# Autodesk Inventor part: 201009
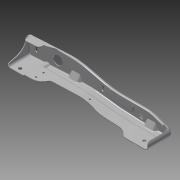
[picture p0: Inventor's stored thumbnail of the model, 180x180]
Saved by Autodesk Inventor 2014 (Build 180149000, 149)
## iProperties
Created: 2007-10
Part Number: 201009
Document SubType Name: Modeling
Designer: MM
Density: 7.85 g/cm^3
Mass: 1039.33 g
Surface Area: 1235.3 cm^2
Volume: 132.398 cm^3
Material: Steel
Description: TOP FRAME RIGHT SIDE PLATE
Appearance: Steel
Component Category: Lower Component
Author: MM
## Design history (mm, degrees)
sketch "Sketch2"
  geometry: L1 (-10, 0)-(-202.66, 0); L2 (-453.629, -13.843)-(-362.619, -13.843); L3 (-357.385, -13.706)-(-296.395, -10.51); L4 (-293.614, -10.266)-(-217.285, -0.894); L5 (-462.692, -8.069)-(-464.267, -4.692); L6 (-462.96, 10.251)-(-460.669, 13.523); L7 (-455.791, 17.222)-(-418.085, 30.463); L8 (-384.952, 36.111)-(-306.589, 36.111); L9 (-248.228, 43.019)-(-193.772, 56.092); L10 (-135.411, 63)-(-10, 63); L11 (0, 10)-(0, 53); A1 r 10 centre (-452.477, 7.787) between (-455.791, 17.222) and (-460.669, 13.523); A2 r 15 centre (-450.673, 1.647) between (-462.96, 10.251) and (-464.267, -4.692); A3 r 10 centre (-453.629, -3.843) between (-462.692, -8.069) and (-453.629, -13.843); A4 r 40 centre (-298.488, 29.435) between (-296.395, -10.51) and (-293.614, -10.266); A5 r 120 centre (-202.66, -120) between (-202.66, 0) and (-217.285, -0.894); A6 r 250 centre (-306.589, 286.111) between (-306.589, 36.111) and (-248.228, 43.019); A7 r 250 centre (-135.411, -187) between (-135.411, 63) and (-193.772, 56.092); A8 r 10 centre (-10, 53) between (0, 53) and (-10, 63); A9 r 10 centre (-10, 10) between (-10, 0) and (0, 10); A10 r 100 centre (-384.952, -63.889) between (-384.952, 36.111) and (-418.085, 30.463); A11 r 100 centre (-362.619, 86.157) between (-362.619, -13.843) and (-357.385, -13.706); 11 further points
  constraints: 22 end point, 22 point on circle, 22 point on line, 22 tangent, 11 centre point, 5 equal radius, 3 parallel, 1 horizontal, 1 perpendicular
  dimensions: "d0" = 210 distance of point (0, 0) point (-210, 0); "d1" = 85 horizontal distance of point (-210, 0) point (-295, -10.437); "d2" = 7 deg angle of L4 L1; "d3" = 65 horizontal distance of point (-360, -13.843) point (-295, -10.437); "d4" = 4 deg angle of L4 L3; "d5" = 460 horizontal distance of point (0, 0) point (-460, -13.843); "d6" = 65 deg angle of L5 L2; "d7" = 120 deg angle of L5 L6; "d8" = 17 vertical distance of point (-460, -13.843) point (-467.927, 3.157); "d9" = 30 vertical distance of point (-460, -13.843) point (-458.825, 16.157); "d10" = 63 distance of point (0, 0) point (0, 63); "d11" = 165 distance of point (-165, 63) point (0, 63); "d12" = 112 horizontal distance of point (-165, 63) point (-277, 36.111); "d13" = 13.5 deg angle of L10 L9; "d14" = 125 distance of point (-402, 36.111) point (-277, 36.111); "d15" = 10 radius of A1; "d16" = 15 radius of A2; "d17" = 40 radius of A4; "d18" = 120 radius of A5; "d19" = 250 radius of A6; "d26" = 100 radius of A10
extrude "Extrusion1" new body sketch "Sketch2" distance "d20" = 80; taper "d21" = 0 deg
sketch "Sketch3"
  geometry: L1 (0, 0)-(125.411, 0) reference; L2 (-10, 0)-(-10, -80) reference; L3 (125.411, 0)-(-10, -8.282); L4 (125.411, 0)-(-10, 0); L5 (-10, 0)-(-10, -8.282)
  constraints: 6 end point, 1 collinear, 1 perpendicular, 1 point on line
  dimensions: "d22" = 3.5 deg angle of L1 L3
extrude "Extrusion2" cut sketch "Sketch3" stored distance "d23" = 80; taper "d24" = 0 deg
fillet "Fillet1" dims "d25" = 500
sketch "Sketch4"
  geometry: L1 (202.66, 0)-(10, 0) reference; C1 r 8.5 at (60, -4.5); 1 further point
  constraints: 1 centre point
  dimensions: "d27" = 4.5 distance from line of C1.centre L1; "d28" = 60 horizontal distance of point (0, 0) C1.centre; "d29" = 17 diameter of C1
extrude "Extrusion3" cut sketch "Sketch4" stored distance "d30" = 80; taper "d31" = 0 deg
sketch "Sketch5"
  geometry: L1 (202.66, 0)-(67.211, 0) reference; L2 (293.614, -10.266)-(217.285, -0.894) reference; L3 (357.385, -13.706)-(296.395, -10.51) reference; L4 (453.629, -13.843)-(362.619, -13.843) reference; L5 (52.789, 0)-(10, 0) reference; L6 (60, -4.5)-(60, 4); L7 (202.66, 4)-(60, 4); L8 (461.629, -9.843)-(362.619, -9.843); L9 (357.594, -9.712)-(296.604, -6.515); L10 (294.101, -6.296)-(217.772, 3.076); A1 r 8.5 centre (60, -4.5) between (67.211, 0) and (52.789, 0) reference; A2 r 120 centre (202.66, -120) between (217.285, -0.894) and (202.66, 0) reference; A3 r 40 centre (298.488, 29.435) between (293.614, -10.266) and (296.395, -10.51) reference; A4 r 100 centre (362.619, 86.157) between (357.385, -13.706) and (362.619, -13.843) reference; A5 r 10 centre (453.629, -3.843) between (453.629, -13.843) and (462.692, -8.069) reference; A6 r 124 centre (202.66, -120) between (217.772, 3.076) and (202.66, 4); A7 r 96 centre (362.619, 86.157) between (357.594, -9.712) and (362.619, -9.843); A8 r 36 centre (298.488, 29.435) between (294.101, -6.296) and (296.604, -6.515); 1 further point
  constraints: 10 end point, 8 point on circle, 3 centre point, 2 parallel, 1 perpendicular, 1 tangent, 3 other
  dimensions: "d32" = 4 distance between parallel lines of L4 L8
extrude "Extrusion4" cut sketch "Sketch5" distance "d33" = 55; taper "d34" = 0 deg
fillet "Fillet4" dims "d38" = 10
fillet "Fillet5" dims "d39" = 10
fillet "Fillet6" dims "d40" = 3
fillet "Fillet7" dims "d41" = 3
workplane "Work Plane1"
sketch "Sketch10"
  geometry: L1 (-10, 58)-(-10, 80) reference; L2 (-10, 80)-(52.574, 80) reference; L3 (52.574, 80)-(52.574, 0) reference; L4 (52.574, 0)-(-6, 0) reference; L5 (-6, 0)-(-6, 52.343) reference; L6 (-10, 68)-(15.981, 83); L7 (15.981, 83)-(-10, 83); L8 (-10, 83)-(-10, 68); A1 r 3 centre (-9, 52.343) between (-6, 52.343) and (-8, 55.172) reference; A2 r 3 centre (-7, 58) between (-10, 58) and (-8, 55.172) reference; 1 further point
  constraints: 6 end point, 2 point on line, 1 collinear, 1 perpendicular
  dimensions: "d89" = 12 distance of L6.start point (-10, 80); "d90" = 60 deg angle of L1 L6; "d91" = 15 distance of L7.end L6.start
extrude "Extrusion9" cut sketch "Sketch10" stored distance "d92" = 40; taper "d93" = 0 deg
chamfer "Chamfer2" distance "d97" = 8; stored, may be unused: second distance "d98" = 20.48336, angle "d99" = 60 deg
chamfer "Chamfer3" distance "d100" = 8; stored, may be unused: second distance "d101" = 20.48336, angle "d102" = 60 deg
fillet "Fillet13" dims "d103" = 5
fillet "Fillet14" dims "d104" = 5
workplane "Work Plane2"
sketch "Sketch11"
  geometry: L1 (-23.843, 58)-(-23.843, 80) reference; L2 (-23.843, 80)-(24.973, 80) reference; L3 (24.973, 0)-(-19.843, 0) reference; L4 (-19.843, 0)-(-19.843, 52.343) reference; L5 (-23.843, 68)-(2.138, 83); L6 (2.138, 83)-(-23.843, 83); L7 (-23.843, 83)-(-23.843, 68); L8 (24.973, 80)-(24.973, 0) reference; A1 r 3 centre (-22.843, 52.343) between (-19.843, 52.343) and (-21.843, 55.172) reference; A2 r 3 centre (-20.843, 58) between (-23.843, 58) and (-21.843, 55.172) reference; 1 further point
  constraints: 6 end point, 1 collinear, 1 perpendicular, 1 point on line
  dimensions: "d106" = 12 distance of L5.start L1.end; "d107" = 60 deg angle of L5 L1; "d108" = 15 distance from line of L6 L5.start
extrude "Extrusion10" cut sketch "Sketch11" stored distance "d109" = 40; taper "d110" = 0 deg
chamfer "Chamfer4" distance "d111" = 8; stored, may be unused: second distance "d112" = 20.48336, angle "d113" = 60 deg
fillet "Fillet15" dims "d114" = 5
fillet "Fillet16" dims "d115" = 5
fillet "Fillet8" dims "d42" = 5
shell "Shell1" dims "d43" = 2.2
sketch "Sketch6"
  geometry: L1 (0, 0)-(43, 0) reference; L2 (43, 67.014)-(43, 0) reference; L3 (44.783, 61.182)-(35.908, 59.229); L4 (53, 67.32)-(53, 0) reference; L5 (52.306, 62)-(53, 62); L6 (16.726, 46.966)-(14.888, 44.549); L7 (6.448, 27.408)-(0.604, 5.902); L8 (-7.116, 0)-(-9, 0); L9 (-9, 0)-(-9, -7); L10 (-9, -7)-(53, -7); L11 (53, 62)-(53, -7); A1 r 33 centre (43, 27) between (35.908, 59.229) and (16.726, 46.966); A2 r 50 centre (54.698, 14.297) between (14.888, 44.549) and (6.448, 27.408); A3 r 35 centre (52.306, 27) between (52.306, 62) and (44.783, 61.182); A4 r 8 centre (-7.116, 8) between (-7.116, 0) and (0.604, 5.902); 4 further points
  constraints: 16 end point, 8 point on circle, 8 point on line, 8 tangent, 4 centre point, 3 perpendicular, 2 parallel, 1 collinear
  dimensions: "d44" = 62 distance from line of L4.end L5; "d45" = 66 diameter of A1; "d46" = 27 distance of A1.centre L1.end; "d47" = 4.5 distance of point (48.5, 62) L5.end; "d48" = 36.8 distance from line of L1 point (9, 36.8); "d49" = 54 distance from line of L4 point (-1, 0); "d50" = 62 distance between parallel lines of L11 L9; "d51" = 7 distance from line of L1.end L10; "d52" = 44 distance from line of L4 point (9, 36.8); "d53" = 50 radius of A2; "d54" = 35 radius of A3; "d55" = 8 radius of A4
extrude "Extrusion5" cut sketch "Sketch6" distance "d56" = 6; taper "d57" = 0 deg
sketch "Sketch7"
  geometry: L1 (0, 67.32)-(110.468, 74.077) reference; L2 (0, 67.32)-(0, 0) reference; L3 (0, 0)-(125.411, 0) reference; L4 (-4, 62)-(-4, 0) reference; L5 (-4, 62)-(-3.713, 62); L6 (2.283, 55.79)-(2.109, 50.802); L7 (10.592, 42.537)-(42.459, 44.486); L8 (49.966, 52.192)-(50.136, 57.07); L9 (54.134, 60.93)-(56.063, 60.93); L10 (57.435, 61.173)-(81.606, 70); L11 (43.814, 70)-(435, 70); L12 (237.061, 80)-(182.605, 80) reference; L13 (435, 70)-(435, 0); L14 (435, 0)-(-4, 0); L15 (-4, 0)-(-4, 62); A1 r 6 centre (-3.713, 56) between (2.283, 55.79) and (-3.713, 62); A2 r 8 centre (10.104, 50.522) between (2.109, 50.802) and (10.592, 42.537); A3 r 8 centre (41.971, 52.472) between (42.459, 44.486) and (49.966, 52.192); A4 r 4 centre (54.134, 56.93) between (54.134, 60.93) and (50.136, 57.07); A5 r 4 centre (56.063, 64.93) between (56.063, 60.93) and (57.435, 61.173); 8 further points
  constraints: 20 end point, 15 point on line, 10 point on circle, 10 tangent, 5 centre point, 4 parallel, 2 collinear, 2 equal radius, 2 perpendicular
  dimensions: "d58" = 10 distance between parallel lines of L11 L12; "d59" = 6.5 distance of L4.start point (2.5, 62); "d60" = 20 vertical distance of point (2.5, 62) point (1.802, 42); "d61" = 88 deg angle of L5 L6; "d62" = 48 distance of point (1.802, 42) point (49.712, 44.93); "d63" = 16 vertical distance of point (49.712, 44.93) point (50.271, 60.93); "d64" = 6.5 distance of point (50.271, 60.93) point (56.771, 60.93); "d65" = 31 distance from line of L10.end L8; "d66" = 435 distance between parallel lines of L2 L13; "d67" = 6 radius of A1; "d68" = 8 radius of A2; "d69" = 4 radius of A4
extrude "Extrusion6" cut sketch "Sketch7" distance "d72" = 45; taper "d73" = 0 deg
sketch "Sketch9"
  geometry: L1 (445, 21.011)-(445, 18.68) reference; L2 (445, 18.68)-(455.062, 15.146) reference; L3 (458.867, 12.261)-(461.158, 8.989) reference; L4 (445, 21.011)-(455.791, 17.222) reference; L5 (460.669, 13.523)-(458.867, 12.261); A1 r 7.8 centre (452.477, 7.787) between (458.867, 12.261) and (455.062, 15.146) reference; A2 r 10 centre (452.477, 7.787) between (460.669, 13.523) and (455.791, 17.222) reference; 1 further point
  constraints: 2 end point, 1 perpendicular
extrude "Extrusion7" cut sketch "Sketch9" distance "d75" = 73; taper "d76" = 0 deg
sketch "Sketch8"
  geometry: L1 (156.108, -22.121)-(101.652, -9.047) reference; L2 (293.346, -29.089)-(214.983, -29.089) reference; L3 (353.394, -44.32)-(325.749, -34.613) reference; L4 (43.804, -8.2)-(5, -8.2); L5 (351.406, -49.981)-(323.761, -40.274); L6 (293.346, -35.089)-(214.983, -35.089); L7 (154.707, -27.955)-(100.251, -14.881); L8 (353.394, -44.32)-(351.406, -49.981); L9 (43.804, -2.2)-(0, -2.2) reference; L10 (5, -8.2)-(5, -2.2); L11 (0, 0)-(0, -2.2) reference; A1 r 247.8 centre (43.804, -250) between (101.652, -9.047) and (43.804, -2.2) reference; A2 r 252.2 centre (214.983, 223.111) between (156.108, -22.121) and (214.983, -29.089) reference; A3 r 97.8 centre (293.346, -126.889) between (325.749, -34.613) and (293.346, -29.089) reference; A4 r 91.8 centre (293.346, -126.889) between (323.761, -40.274) and (293.346, -35.089); A5 r 258.2 centre (214.983, 223.111) between (154.707, -27.955) and (214.983, -35.089); A6 r 241.8 centre (43.804, -250) between (100.251, -14.881) and (43.804, -8.2); 1 further point
  constraints: 12 end point, 6 point on circle, 3 centre point, 2 perpendicular, 1 point on line, 4 other
  dimensions: "d77" = 6 distance between parallel lines of L3 L5; "d78" = 6 radial gap between concentric circles of A3 A4; "d81" = 5 distance between parallel lines of L11 L10; "d82" = 6 distance between parallel lines of L9 L4
extrude "Extrusion8" join sketch "Sketch8" distance "d79" = 2.2; taper "d80" = 0 deg
fillet "Fillet9" dims "d83" = 2.5
fillet "Fillet10" dims "d84" = 0.3
fillet "Fillet11" dims "d85" = 10
fillet "Fillet12" dims "d86" = 5
sketch "Sketch12"
  geometry: L1 (38.511, 67.32)-(38.511, 0) reference; L2 (0, 0)-(-28.281, 0); L3 (-47.011, 3.641)-(-48.511, 4.247); L4 (-63.601, 18.819)-(-63.95, 19.603); L5 (-74.494, 26.715)-(-168.594, 30.001); L6 (-205.015, 26.814)-(-216.579, 24.356); L7 (-247.766, 21.078)-(-298.348, 21.078); L8 (-328.989, 6.79)-(-349.791, -18); L9 (-349.791, -18)-(0, -18); L10 (0, -18)-(0, 0); L11 (-11.489, 0)-(-154.15, 0) reference; A1 r 10 centre (-186.122, 20.607) between (-185.773, 30.6) and (-188.201, 30.388); A2 r 50 centre (-28.281, 50) between (-47.011, 3.641) and (-28.281, 0); A3 r 28 centre (-38.022, 30.208) between (-63.601, 18.819) and (-48.511, 4.247); A4 r 12 centre (-74.913, 14.722) between (-63.95, 19.603) and (-74.494, 26.715); A5 r 150 centre (-173.828, -119.908) between (-168.594, 30.001) and (-205.015, 26.814); A6 r 150 centre (-247.766, 171.078) between (-247.766, 21.078) and (-216.579, 24.356); A7 r 40 centre (-298.348, -18.922) between (-298.348, 21.078) and (-328.989, 6.79); 7 further points
  constraints: 18 end point, 14 point on circle, 14 point on line, 14 tangent, 7 centre point, 2 parallel, 2 perpendicular, 1 equal radius
  dimensions: "d116" = 18 distance of L9.end L2.start; "d117" = 38 distance of L2.start point (-38, 0); "d118" = 21 horizontal distance of point (-59, 8.485) point (-38, 0); "d119" = 22 deg angle of L3 L2; "d120" = 8 horizontal distance of point (-59, 8.485) point (-67, 26.453); "d121" = 66 deg angle of L2 L4; "d122" = 120 horizontal distance of point (-187, 30.643) point (-67, 26.453); "d123" = 2 deg angle of L11 L5; "d124" = 45 horizontal distance of point (-232, 21.078) point (-187, 30.643); "d125" = 12 deg angle of L9 L6; "d126" = 85 distance of point (-232, 21.078) point (-317, 21.078); "d127" = 50 deg angle of L8 L7; "d128" = 10 radius of A1; "d129" = 50 radius of A2; "d130" = 28 radius of A3; "d131" = 12 radius of A4; "d132" = 150 radius of A5; "d133" = 40 radius of A7
extrude "Extrusion11" cut sketch "Sketch12" stored distance "d134" = 40; taper "d135" = 0 deg
fillet "Fillet17" dims "d136" = 20
fillet "Fillet18" dims "d137" = 10
sketch "Sketch13"
  geometry: L1 (384.952, -31.111)-(306.589, -31.111) reference; L2 (296.657, 5.517)-(357.647, 8.713) reference; L3 (217.894, -4.068)-(294.223, 5.304) reference; L4 (334.231, -21.656)-(311.461, -21.656); L5 (332.236, -2.132)-(297.659, -3.944); L6 (294.878, -4.187)-(266.95, -7.616); L7 (339.15, -15.762)-(337.417, -6.231); L8 (262.873, -10.836)-(260.164, -18.12); A1 r 255 centre (306.589, -286.111) between (306.589, -31.111) and (247.061, -38.157) reference; A2 r 264.5 centre (306.589, -286.111) between (311.461, -21.656) and (265.625, -24.803); A3 r 40 centre (299.753, -43.889) between (297.659, -3.944) and (294.878, -4.187); A4 r 5 centre (264.851, -19.863) between (260.164, -18.12) and (265.625, -24.803); A5 r 5 centre (267.56, -12.579) between (266.95, -7.616) and (262.873, -10.836); A6 r 5 centre (334.231, -16.656) between (334.231, -21.656) and (339.15, -15.762); A7 r 5 centre (332.498, -7.125) between (337.417, -6.231) and (332.236, -2.132); 7 further points
  constraints: 12 point on circle, 10 end point, 10 tangent, 6 centre point, 6 point on line, 3 equal radius, 1 parallel
  dimensions: "d138" = 9.5 distance between parallel lines of L2 L5; "d139" = 9.5 distance between parallel lines of L3 L6; "d140" = 9.5 radial gap between concentric circles of A1 A2; "d142" = 40 radius of A3; "d144" = 19.7546 vertical distance of point (340.222, -21.656) point (336.63, -1.901); "d145" = 72.69753 horizontal distance of point (263.933, -7.987) point (336.63, -1.901); "d147" = 62.5985 deg angle of L8 L6; "d148" = 5 radius of A4; "d149" = 97.3028 deg angle of L5 L7; "d193" = 42.04198 distance from line of L7 point (377.408, 8.843)
extrude "Extrusion12" cut sketch "Sketch13" distance "d150" = 2.2; taper "d151" = 0 deg
sketch "Sketch14"
  geometry: L1 (32.561, -15.349)-(30.828, -24.881) reference; L2 (25.647, -28.979)-(-8.93, -27.167) reference; L3 (-11.711, -26.924)-(-39.639, -23.495) reference; L4 (-43.716, -20.275)-(-46.425, -12.991) reference; L5 (4.872, -9.455)-(27.641, -9.455) reference; L6 (-48.487, -13.758)-(-45.778, -21.042); L7 (-39.907, -25.679)-(-11.979, -29.108); L8 (-9.045, -29.364)-(25.532, -31.176); L9 (32.993, -25.274)-(34.725, -15.743); L10 (27.641, -7.255)-(4.851, -7.255); A1 r 5 centre (27.641, -14.455) between (32.561, -15.349) and (27.641, -9.455) reference; A2 r 5 centre (25.909, -23.986) between (25.647, -28.979) and (30.828, -24.881) reference; A3 r 40 centre (-6.837, 12.778) between (-11.711, -26.924) and (-8.93, -27.167) reference; A4 r 5 centre (-39.03, -18.532) between (-43.716, -20.275) and (-39.639, -23.495) reference; A5 r 5 centre (-41.739, -11.248) between (-40.965, -6.309) and (-46.425, -12.991) reference; A6 r 264.5 centre (0, 255) between (-40.965, -6.309) and (4.872, -9.455) reference; A7 r 7.2 centre (-39.03, -18.532) between (-45.778, -21.042) and (-39.907, -25.679); A8 r 42.2 centre (-6.837, 12.778) between (-11.979, -29.108) and (-9.045, -29.364); A9 r 7.2 centre (25.909, -23.986) between (25.532, -31.176) and (32.993, -25.274); A10 r 7.2 centre (27.641, -14.455) between (34.725, -15.743) and (27.641, -7.255); A11 r 262.3 centre (0, 255) between (-40.624, -4.135) and (4.851, -7.255); A12 r 7.2 centre (-41.739, -11.248) between (-40.624, -4.135) and (-48.487, -13.758); 1 further point
  constraints: 12 point on circle, 10 end point, 6 centre point, 10 other
  dimensions: "d152" = 2.2 radial gap between concentric circles of A6 A11
extrude "Extrusion13" join sketch "Sketch14" distance "d153" = 2.2; taper "d154" = 0 deg
fillet "Fillet19" dims "d155" = 2.2
fillet "Fillet20" dims "d156" = 2.2
sketch "Sketch15"
  geometry: C1 r 5.25 at (20.905, 14.698); 1 further point
  constraints: 1 centre point
  dimensions: "d157" = 10.5 diameter of C1; "d158" = 65.302 vertical distance of C1.centre point (48.511, 80); "d159" = 27.606 horizontal distance of C1.centre point (48.511, 80)
extrude "Extrusion14" cut sketch "Sketch15" stored distance "d160" = 10; taper "d161" = 0 deg
sketch "Sketch16"
  geometry: C1 r 5.25 at (22.318, -30.122); A1 r 40 centre (106.771, -71.265) between (91.011, -34.5) and (76.329, -45.317) reference; 1 further point
  constraints: 1 centre point
  dimensions: "d162" = 10.5 diameter of C1; "d163" = 84.45243 horizontal distance of C1.centre A1.centre; "d164" = 41.14271 vertical distance of A1.centre C1.centre
extrude "Extrusion15" cut sketch "Sketch16" stored distance "d165" = 10; taper "d166" = 0 deg
fillet "Fillet21" dims "d167" = 2
fillet "Fillet22" dims "d168" = 2
fillet "Fillet23" dims "d169" = 2
workplane "Work Plane3"
  workaxis "Work Axis1"
sketch "Sketch17"
  geometry: A1 r 10 centre (450.673, -1.647) between (458.864, -7.383) and (459.736, 2.579) reference; 3 further points
  constraints: 1 coincident
  dimensions: "d186" = 365.52774 horizontal distance of point (365.528, -1.647) point (0, 0); "d187" = 1.64723 vertical distance of point (0, 0) point (365.528, -1.647)
hole "Hole1" sketch "Sketch17" at (450.673, -1.647), (365.528, -1.647) diameter "d179" = 14.65; stored, may be unused: countersink angle "d183" = 90 deg, drill point angle "d185" = 118 deg; dims "d180" = 6, "d181" = 4, "d182" = 2, "d184" = 8
hole "Hole2" diameter "d204" = 5.9; stored, may be unused: countersink angle "d208" = 90 deg, drill point angle "d210" = 118 deg; dims "d202" = 10, "d203" = 15, "d205" = 6, "d206" = 4, "d207" = 2, "d209" = 8
hole "Hole3" diameter "d213" = 5.9; stored, may be unused: countersink angle "d217" = 90 deg, drill point angle "d219" = 118 deg; dims "d211" = 15 (derived), "d212" = 120, "d214" = 6, "d215" = 4, "d216" = 2, "d218" = 8
hole "Hole4" diameter "d222" = 5.9; stored, may be unused: countersink angle "d226" = 90 deg, drill point angle "d228" = 118 deg; dims "d220" = 120 (derived), "d221" = 40, "d223" = 6, "d224" = 4, "d225" = 2, "d227" = 8
sketch "Sketch21"
  geometry: C1 r 15 at (87.294, 25.958)
  constraints: 1 centre point
  dimensions: "d232" = 30 diameter of C1
extrude "Extrusion17" cut sketch "Sketch21" stored distance "d233" = 10; taper "d234" = 0 deg
sketch "Sketch22"
  geometry: L1 (-124.405, 47.396)-(-123.092, 41.552) reference; L2 (-122.046, 33.112)-(-121.898, 31.274) reference; L3 (-121.15, 12.092)-(-121.054, 5) reference; L4 (-120.674, 5)-(-121.054, 5) reference; L5 (-120.674, 48)-(-120.674, 5) reference; L6 (-120.674, 48)-(-124.5, 48) reference; L7 (-98.674, 18.302)-(-98.674, 36.302); L8 (-92.674, 36.302)-(-92.674, 18.302); A1 r 3 centre (-95.674, 36.302) between (-92.674, 36.302) and (-98.674, 36.302); A2 r 3 centre (-95.674, 18.302) between (-98.674, 18.302) and (-92.674, 18.302); 3 further points; 3 other entities
  constraints: 4 end point, 4 point on circle, 4 tangent, 2 centre point, 2 parallel, 3 other
  dimensions: "d235" = 6 distance between parallel lines of L8 L7; "d236" = 18 distance of A1.centre A2.centre; "d237" = 25 distance from line of L5 A2.centre; "d238" = 25 vertical distance of point (-123.893, -6.698) A2.centre
extrude "Extrusion18" cut sketch "Sketch22" stored distance "d239" = 10; taper "d240" = 0 deg
sketch "Sketch23"
  geometry: L1 (-95.674, 18.302)-(-95.674, 36.302); A1 r 3 centre (-95.674, 36.302) between (-92.674, 36.302) and (-98.674, 36.302) reference; A2 r 3 centre (-95.674, 18.302) between (-98.674, 18.302) and (-92.674, 18.302) reference; 3 further points
  constraints: 2 coincident, 2 end point, 1 midpoint, 1 vertical
sketch "Sketch24"
  geometry: L1 (234.608, -31.107)-(234.608, -13.107); L2 (240.608, -13.107)-(240.608, -31.107); A1 r 3 centre (237.608, -13.107) between (240.608, -13.107) and (234.608, -13.107); A2 r 3 centre (237.608, -31.107) between (234.608, -31.107) and (240.608, -31.107)
  constraints: 4 end point, 4 point on circle, 4 tangent, 2 centre point, 1 parallel, 1 vertical
  dimensions: "d241" = 18 distance of A1.centre A2.centre; "d242" = 6 distance between parallel lines of L2 L1
extrude "Extrusion19" cut sketch "Sketch24" stored distance "d243" = 10; taper "d244" = 0 deg
sketch "Sketch25"
  geometry: L1 (237.608, -31.107)-(237.608, -13.107); A1 r 3 centre (237.608, -31.107) between (234.608, -31.107) and (240.608, -31.107) reference; A2 r 3 centre (237.608, -13.107) between (240.608, -13.107) and (234.608, -13.107) reference; 3 further points
  constraints: 2 coincident, 2 end point, 1 midpoint, 1 vertical
body "Solid1"
node "Projected Loop1"
node "Project Cut Edges1"
node "Project Cut Edges2"
other parameters: "d178" = 90 deg, "d229" = 0, "d230" = 0, "d231" = 0
